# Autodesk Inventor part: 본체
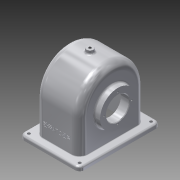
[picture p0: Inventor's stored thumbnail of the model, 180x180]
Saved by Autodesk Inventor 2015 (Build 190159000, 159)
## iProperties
Created: 2016-01
Part Number: 본체
Material: 알루미늄 6061
Document SubType Name: Modeling
Designer: Administrator
Density: 2.7 g/cm^3
Appearance: 알루미늄 - 평지
Mass: 806.765 g
Surface Area: 999.207 cm^2
Volume: 298.802 cm^3
Author: Administrator
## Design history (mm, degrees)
sketch "스케치1"
  geometry: L1 (-52, 70)-(52, 70); L2 (52, 70)-(52, -70); L3 (52, -70)-(-52, -70); L4 (-52, -70)-(-52, 70); C1 r 2.5 at (-44, 62); C2 r 2.5 at (44, 62); C3 r 2.5 at (-44, -62); C4 r 2.5 at (44, -62); 3 further points
  constraints: 8 end point, 4 centre point, 2 midpoint, 2 parallel, 1 horizontal, 1 horizontal alignment, 1 perpendicular, 1 vertical alignment
  dimensions: "d0" = 104 distance between parallel lines of L2 L4; "d1" = 140 distance between parallel lines of L3 L1; "d2" = 5 diameter of C1; "d3" = 8 distance from line of C1.centre L1; "d4" = 8 distance from line of L4 C1.centre
extrude "돌출1" new body sketch "스케치1" distance "d5" = 7; taper "d6" = 0 deg
sketch "스케치3"
  geometry: L1 (-57, 64)-(-57, 0); L2 (57, 64)-(57, 0); L3 (70, 0)-(-70, 0) reference; A1 r 57 centre (0, 64) between (57, 64) and (-57, 64); 1 further point
  constraints: 4 end point, 2 point on circle, 2 point on line, 2 vertical, 1 centre point, 1 tangent
  dimensions: "d7" = 114 diameter of A1; "d8" = 64 distance from line of L3 A1.centre
extrude "돌출2" join sketch "스케치3" stored distance "d9" = 77; taper "d10" = 0 deg
node "작업 평면1"
sketch "스케치5"
  geometry: L1 (0, 70)-(0, -70) reference; C1 r 31 at (60, 0); 1 further point
  constraints: 1 centre point
  dimensions: "d13" = 62 diameter of C1; "d82" = 60 distance from line of L1 C1.centre
extrude "돌출3" join sketch "스케치5" stored distance "d14" = 77; taper "d15" = 0 deg
sketch "스케치6"
  geometry: L1 (57, 7)-(57, 64) reference; L2 (-57, 64)-(-57, 7) reference; L3 (-51, 0)-(-51, 64); L4 (51, 64)-(51, 0); L5 (70, 0)-(-70, 0) reference; A1 r 57 centre (0, 64) between (57, 64) and (-57, 64) reference; A2 r 51 centre (0, 64) between (51, 64) and (-51, 64); 1 further point
  constraints: 4 end point, 2 point on circle, 2 point on line, 1 centre point
  dimensions: "d16" = 6 radial gap between concentric circles of A1 A2
extrude "돌출4" cut sketch "스케치6" stored distance "d17" = 67; taper "d18" = 0 deg
node "작업 평면2"
sketch "스케치8"
  geometry: L1 (0, 51)-(0, -51) reference; C1 r 28 at (-60, 0); 1 further point
  constraints: 1 centre point
  dimensions: "d85" = 60 distance from line of L1 C1.centre
extrude "돌출5" join sketch "스케치8" stored distance "d21" = 67; taper "d22" = 40 deg
sketch "스케치9"
  geometry: L1 (53, 57)-(53, -57); L2 (-4, -57)-(53, -57); L3 (60, 70)-(60, -70) reference; C1 r 20 at (0, 0); 1 further point
  constraints: 1 centre point
  dimensions: "d23" = 40 diameter of C1; "d83" = 60 distance from line of L3 C1.centre
extrude "돌출6" cut sketch "스케치9" stored distance "d24" = 67; taper "d25" = 0 deg
sketch "스케치11"
  geometry: L1 (53, -57)-(53, 57); L2 (53, -57)-(-4, -57); L3 (-4, 57)-(53, 57); L4 (60, 51)-(60, -51) reference; C1 r 20 at (0, 0); A1 r 57.14 centre (0, 0) between (-4, 57) and (-4, -57); 1 further point
  constraints: 2 centre point, 2 point on circle, 1 coincident
  dimensions: "d31" = 40 diameter of C1; "d104" = 60 distance from line of L4 A1.centre
extrude "돌출7" cut sketch "스케치11" distance "d32" = 16; taper "d33" = 0 deg
node "작업 평면3"
sketch "스케치12"
  geometry: C1 r 6 at (0, 0); 1 further point
  constraints: 1 centre point, 1 coincident
  dimensions: "d35" = 12 diameter of C1
extrude "돌출8" join sketch "스케치12" stored distance "d36" = 16; taper "d37" = 0 deg
sketch "스케치13"
  geometry: 2 further points
  constraints: 1 coincident
hole "구멍1" sketch "스케치13" at (0, 0) diameter "d38" = 4.459; stored, may be unused: countersink angle "d42" = 90 deg, drill point angle "d44" = 118 deg; dims "d39" = 10, "d40" = 4, "d41" = 2, "d43" = 12.8
sketch "스케치14" dims "d45" = 48
  geometry: L1 (60, -51)-(60, 51) reference; 4 further points
  constraints: 1 coincident, 1 horizontal alignment, 2 other
  dimensions: "d84" = 60 distance from line of L1 point (0, 0)
hole "구멍2" sketch "스케치14" at (-24, 0) diameter "d46" = 2.459; stored, may be unused: countersink angle "d50" = 90 deg, drill point angle "d52" = 118 deg; dims "d47" = 6, "d48" = 4, "d49" = 2, "d51" = 8
sketch "스케치17"
  geometry: L1 (90.5, -7)-(-13.5, -7) reference; 3 further points
  constraints: 1 midpoint, 1 vertical alignment, 1 other
  dimensions: "d70" = 30 distance from line of L1 point (38.5, 23)
feature "엠보싱1" sketch "스케치17" dims "d0" = 104, "d1" = 140, "d2" = 5, "d3" = 8, "d4" = 8, "d71" = 0.5, "d72" = 0
chamfer "모따기1" distance "d73" = 1; stored, may be unused: second distance "d74" = 2, angle "d75" = 45 deg
fillet "모깎기1" dims "d76" = 1, "d77" = 9, "d78" = 14, "d79" = 8, "d80" = 3
sketch "스케치20"
  geometry: L1 (38.5, 97.416)-(38.5, 60); L2 (35.5, 60)-(35.5, 80); L3 (35.5, 60)-(38.5, 60); L4 (35.5, 94.899)-(38.5, 97.416); L5 (35.5, 94.899)-(35.5, 60); L6 (35.5, 40)-(35.5, 80) reference; L7 (19.5, 40)-(19.5, 80) reference; L8 (19.5, 60)-(40.609, 60); L9 (33.5, 64)-(24.5, 64) reference; L10 (24.5, 64)-(24.5, 64) reference; L11 (33.5, 64)-(24.5, 64) reference; L12 (33.5, 64)-(33.5, 64) reference; L13 (19.5, 88)-(32.428, 98.848) reference; L14 (38.5, 107)-(38.5, 64) reference; 1 further point
  constraints: 12 end point, 3 collinear, 2 horizontal, 1 midpoint
  dimensions: "d105" = 5 distance between parallel lines of L13 L4
revolve "회전2" sketch "스케치20" stored, may be unused: angle "d88" = 90 deg
sketch "스케치21" dims "d89" = 56
  geometry: C1 r 34.899 at (0, 0) reference; 3 further points
  constraints: 1 coincident, 1 horizontal alignment, 2 other
hole "구멍4" sketch "스케치21" at (28, 0) diameter "d90" = 2.459; stored, may be unused: countersink angle "d94" = 90 deg, drill point angle "d96" = 118 deg; dims "d91" = 7, "d92" = 4, "d93" = 2, "d95" = 9
fillet "모깎기2" dims "d100" = 3
chamfer "모따기2" distance "d101" = 1; stored, may be unused: second distance "d102" = 2, angle "d103" = 45 deg
node "솔리드1"
pattern_circular "원형 패턴1" dims angle "d54" = 360 deg
pattern_circular "원형 패턴3" dims angle "d98" = 360 deg
node "투영된 루프6"
node "투영된 루프7"
other parameters: "d12" = -87, "d19" = 14, "d34" = -127
